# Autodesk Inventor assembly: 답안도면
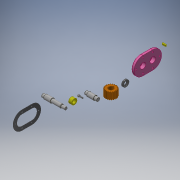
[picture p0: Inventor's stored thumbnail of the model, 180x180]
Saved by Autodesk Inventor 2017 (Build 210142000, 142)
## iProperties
Part Number: 답안도면
Material: 일반
Document SubType Name: Assembly
Designer: 00-00
Author: 00-00
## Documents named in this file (10)
- C:\Users\00-00\Desktop\700906V1012\답안도면.iam
- C:\Users\00-00\Desktop\700906V1012\개스킷.ipt
- C:\Users\00-00\Desktop\700906V1012\메인축.ipt
- C:\Users\00-00\Desktop\700906V1012\베어링부시.ipt
- C:\Users\00-00\Desktop\700906V1012\볼트 M5.ipt
- C:\Users\00-00\Desktop\700906V1012\서브축.ipt
- C:\Users\00-00\Desktop\700906V1012\스퍼기어.ipt
- C:\Users\00-00\Desktop\700906V1012\오일 실 16 28 7.ipt
- C:\Users\00-00\Desktop\700906V1012\커버.ipt
- C:\Users\00-00\Desktop\700906V1012\키 6 x 6 x 18.ipt
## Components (1 placed, 1 different names)
1. 개스킷:1
